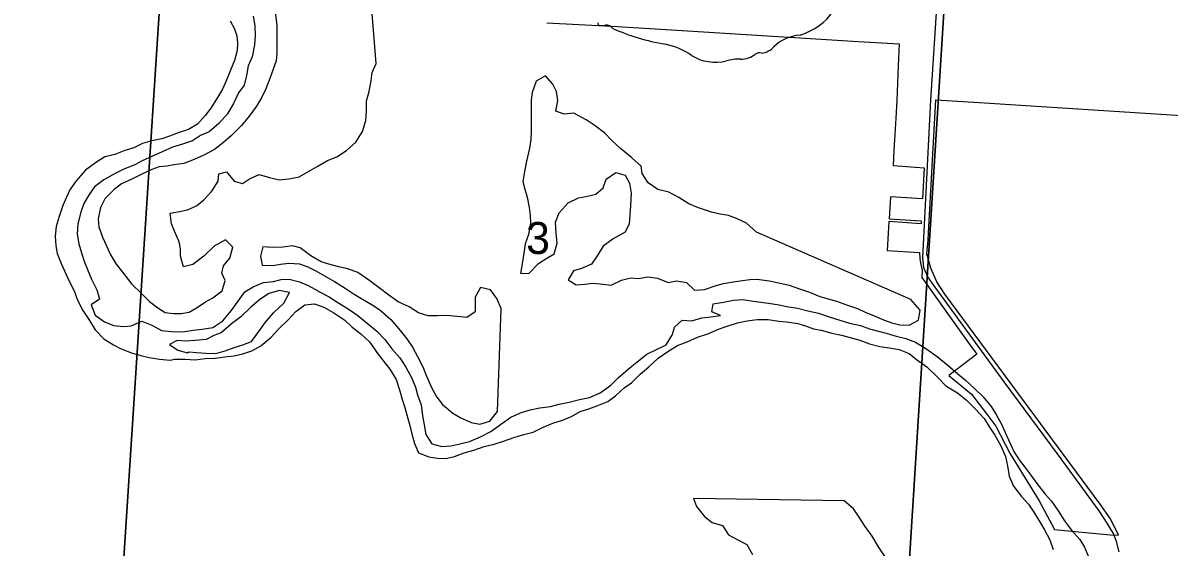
# Model space of a CAD drawing. Extents: x 114843 to 284848, y 317643 to 566895.
# Drawn here: x 207453 to 215376, y 334768 to 338396 of the extents above; entities that cross this region are included whole.
import ezdxf

# ---------------------------------------------------------------- set-up
doc = ezdxf.new("R2010")
doc.units = 0
for name, color, linetype in [('GM_X_Corporation', 7, 'Continuous'), ('GM_X_County_Road', 7, 'Continuous'), ('GM_X_Major_River', 7, 'Continuous'), ('GM_X_Minor_Lake', 7, 'Continuous'), ('GM_X_Section', 7, 'Continuous'), ('GM_X_Section_Text', 7, 'Continuous'), ('GM_X_State_Shield', 7, 'Continuous')]:
    doc.layers.add(name, color=color, linetype=linetype)

msp = doc.modelspace()

# ---------------------------------------------------------------- linework, layer by layer
at = {"layer": 'GM_X_Corporation'}
msp.add_lwpolyline([(211073.8, 338397.3), (211296.2, 338384.8), (211564.6, 338369.8), (211597.2, 338367.9), (211751, 338358.5), (211935.5, 338347.1), (212121.3, 338335.7), (212305.8, 338324.4), (212490.4, 338313), (212674.9, 338301.7), (212859.5, 338290.4), (213044.1, 338279), (213227.8, 338267.7), (213511.2, 338250.3), (213504.3, 338099), (213498.8, 337978.1), (213493.3, 337858.8), (213487, 337737.3), (213480.4, 337625.8), (213474.5, 337512.6), (213469, 337409.6), (213683.7, 337393.9), (213671.5, 337178.1), (213450.7, 337192.3), (213440.2, 337041), (213662.9, 337026.4), (213661.7, 337005), (213438.8, 337021.3), (213434.1, 336937.9), (213427.5, 336820.3), (213650.7, 336807.4), (213653.1, 336765.7), (213655.9, 336746.4), (213659.6, 336724.5), (213670.1, 336684.1), (213666.9, 336633), (213993.3, 336175.5), (214046.6, 336103.2), (213853.5, 335955.2), (214011.3, 335825.5), (214116.8, 335687.1), (214179.1, 335605.3), (214277.2, 335413.6), (214477.3, 335088.3), (214585.3, 334889.3), (214968.3, 334852.8), (215025.8, 334851.3), (214971.2, 334963.4), (214900.4, 335064.4), (214113.6, 336129.7), (213826.5, 336518.5), (213770.9, 336604.5), (213729.4, 336698), (213702.8, 336796.8), (213707.4, 336844.4), (213710.8, 336892.1), (213713, 336939.9), (213765, 337864.5), (214101.2, 337843.6), (215892.9, 337727.1)], dxfattribs=at)
at = {"layer": 'GM_X_County_Road'}
msp.add_lwpolyline([(215030.3, 334736.4), (215012.1, 334807.6), (214992.5, 334862.7), (214948.8, 334934.4), (214893, 335018), (214604.4, 335414.4), (214235.9, 335911.2), (213741.2, 336591.8), (213709.7, 336639.6), (213680.4, 336701.8), (213675.1, 336771.4), (213729.6, 337861.8), (213798.8, 338930.7), (213818.3, 339221.3)], dxfattribs=at)
at = {"layer": 'GM_X_Major_River'}
for points in [[(209044.3, 338442.2), (209056.7, 338376.2), (209059.1, 338306.1), (209053.5, 338244), (209038, 338161.8), (209010.4, 338097.6), (208998.8, 338031.4), (208983.3, 337965.2), (208943.6, 337912.9), (208908.1, 337838.6), (208866.6, 337766.3), (208807.1, 337699.8), (208741.5, 337641.3), (208679.7, 337616.9), (208626, 337580.5), (208556.2, 337556.1), (208486.4, 337535.6), (208414.7, 337503.2), (208349, 337474.7), (208277.3, 337442.2), (208225.5, 337413.9), (208149.8, 337383.4), (208090, 337353), (208012.4, 337310.4), (207946.7, 337262), (207911.1, 337207.7), (207873.5, 337145.4), (207853.9, 337085.2), (207832.4, 337004.9), (207828.9, 336934.8), (207839.3, 336866.8), (207857.6, 336804.8), (207878, 336740.9), (207900.3, 336689), (207926.6, 336623), (207965, 336549.2), (207983.4, 336483.2), (207925.7, 336444.8), (207952.1, 336372.9), (208016.3, 336327.2), (208082.4, 336301.6), (208148.3, 336294), (208200.2, 336300.3), (208276, 336330.8), (208344.1, 336303.2), (208410.2, 336267.6), (208480.1, 336260), (208558.1, 336258.5), (208629.9, 336268.9), (208691.8, 336275.3), (208765.6, 336287.8)], [(208886.7, 338409.2), (208915, 338355.3), (208931.3, 338305.3), (208935.6, 338255.3), (208933.9, 338205.2), (208916.3, 338135), (208888.7, 338068.8), (208861.2, 338000.5), (208833.6, 337936.3), (208790.1, 337867.9), (208752.5, 337805.6), (208712.8, 337755.3), (208659.3, 337694.9), (208597.6, 337658.5), (208533.8, 337638.1), (208466, 337611.6), (208412.2, 337593.2), (208344.3, 337580.8), (208278.5, 337562.4), (208220.8, 337532), (208157, 337513.6), (208089.2, 337485.1), (208019.4, 337468.7), (207953.7, 337428.2), (207886.1, 337375.7), (207820.6, 337303.2), (207777.1, 337240.9), (207753.4, 337190.7), (207729.8, 337132.5), (207704.3, 337056.2), (207682.7, 336988), (207675.1, 336919.9), (207679.5, 336853.8), (207689.8, 336799.8), (207716.2, 336729.9), (207740.5, 336680), (207772.9, 336608.1), (207807.3, 336542.2), (207829.6, 336476.2), (207866, 336406.4), (207912.4, 336336.6), (207952.7, 336270.7), (208013, 336209), (208079.2, 336167.4), (208131.3, 336139.7), (208203.4, 336112.1), (208267.4, 336094.5), (208325.4, 336080.8), (208397.4, 336069.2), (208471.4, 336061.7)], [(208765.6, 336287.8), (208835.3, 336334.3), (208892.8, 336402.7), (208940.3, 336471.1), (208987.9, 336535.5), (209045.6, 336569.9), (209115.3, 336600.3), (209185.2, 336606.8), (209237.1, 336619.1), (209293, 336621.5), (209365, 336603.9), (209425.1, 336578.2), (209495.2, 336538.6)], [(209295.5, 336529.4), (209227.5, 336542.9), (209151.8, 336522.5), (209088.1, 336480), (209028.5, 336427.6), (208959, 336361.1), (208895.3, 336312.6), (208823.8, 336252.1), (208772, 336231.7), (208720.2, 336205.4), (208644.3, 336198.9), (208580.4, 336192.5), (208518.5, 336198.1), (208466.7, 336169.8), (208522.9, 336130.1), (208590.9, 336112.5)], [(208590.9, 336112.5), (208600.9, 336118.5), (208652.8, 336114.9), (208716.8, 336109.2), (208786.7, 336107.7), (208850.5, 336126.1), (208920.3, 336152.6), (208972.1, 336168.9), (209033.9, 336191.3), (209083.4, 336259.7), (209129, 336324.1), (209184.5, 336388.5), (209256, 336457), (209295.5, 336529.4)], [(209495.2, 336538.6), (209503.3, 336534.6), (209569.4, 336501), (209629.6, 336461.3), (209701.7, 336417.7), (209767.9, 336370.1), (209832.2, 336318.4), (209900.4, 336262.7), (209954.7, 336205), (210003, 336141.2), (210057.4, 336077.5), (210099.7, 336013.6), (210138.1, 335941.8), (210166.5, 335873.9), (210180.7, 335821.9), (210205.1, 335751.9), (210215.6, 335675.9), (210227.9, 335613.9), (210238.3, 335547.9), (210280.7, 335482), (210348.7, 335464.4), (210410.6, 335468.8), (210472.4, 335483.2), (210540.3, 335499.6), (210616, 335532.2), (210687.7, 335568.6), (210755.3, 335617.1), (210824.9, 335667.6), (210892.6, 335698.1), (210960.4, 335718.5), (211026.3, 335731), (211100.1, 335741.4), (211160, 335757.8), (211229.8, 335770.3), (211299.6, 335790.7), (211369.4, 335803.2), (211443.2, 335835.7), (211516.8, 335888.2), (211568.4, 335940.6), (211635.9, 335999.1), (211699.6, 336049.5), (211765.2, 336104), (211832.9, 336134.5), (211898.6, 336168.9), (211944.1, 336239.3), (211957.8, 336289.4), (212009.4, 336337.8), (212077.4, 336334.2), (212145.2, 336354.7), (212209.1, 336361.1), (212274.9, 336371.5), (212214.9, 336397.1), (212224.5, 336451.3), (212296.4, 336463.7), (212364.2, 336478.2), (212430.1, 336480.6), (212502.1, 336469), (212554, 336463.3), (212608, 336455.6), (212682, 336444.1), (212734, 336432.4), (212808, 336422.8), (212878, 336403.2), (212952, 336387.7), (213026.1, 336362.1), (213100.1, 336338.5), (213168.2, 336318.9), (213242.2, 336301.3), (213306.3, 336279.7), (213368.3, 336262.1), (213420.3, 336248.4), (213490.4, 336226.8), (213556.4, 336211.1), (213622.5, 336185.5), (213702.6, 336137.9), (213772.9, 336088.3), (213849.1, 336024.7), (213915.4, 335967), (213969.6, 335923.3), (214031.9, 335865.6), (214090.2, 335807.9), (214146.5, 335740.1), (214180.8, 335686.3), (214219.2, 335614.4), (214251.6, 335540.5), (214279.9, 335480.6), (214304.2, 335430.7), (214340.5, 335372.8), (214378.8, 335321), (214421.1, 335265.2), (214461.3, 335207.3), (214519.7, 335135.6), (214564, 335085.8), (214610.3, 335018), (214652.7, 334950.2), (214701, 334884.4), (214759.3, 334820.6), (214791.6, 334768.8), (214822, 334696.8)], [(208471.4, 336061.7), (208503.3, 336067.9), (208575.2, 336068.3), (208643.1, 336064.7), (208713, 336073.2), (208782.9, 336075.6), (208848.8, 336084), (208912.6, 336092.4), (208972.5, 336104.8), (209036.3, 336127.2), (209098, 336161.7), (209167.6, 336218.2), (209221.1, 336278.6), (209288.7, 336343.1), (209340.3, 336399.5), (209401.9, 336445.9), (209467.8, 336452.3), (209533.9, 336428.7), (209602, 336389.1), (209678.2, 336339.5), (209728.5, 336289.7), (209788.7, 336244), (209851, 336186.3), (209899.3, 336114.5), (209937.6, 336064.7), (209989.9, 335998.9), (210034.3, 335929.1), (210056.7, 335857.2), (210077.1, 335783.2), (210093.4, 335733.2), (210113.8, 335659.2), (210128.1, 335609.3), (210142.4, 335551.3), (210158.8, 335485.3), (210187.1, 335421.4), (210259.2, 335393.8), (210333.2, 335380.2), (210385.2, 335382.5), (210437, 335394.9), (210502.8, 335421.3), (210570.6, 335439.8), (210640.4, 335464.2), (210710.2, 335480.7), (210776, 335501.1), (210845.7, 335525.6), (210907.6, 335544), (210979.3, 335564.4), (211045.1, 335596.9), (211116.8, 335625.4), (211182.6, 335645.8), (211246.4, 335672.2), (211306.1, 335706.6), (211357.9, 335723), (211427.7, 335747.4), (211497.4, 335775.9), (211549.2, 335814.3), (211608.7, 335870.7), (211660.5, 335905.1), (211720, 335965.5), (211779.7, 336016), (211845.2, 336076.5), (211910.9, 336120.9), (211978.5, 336163.4), (212044.3, 336189.8), (212116, 336220.3), (212187.8, 336244.8), (212261.5, 336275.3), (212315.3, 336295.6), (212393.1, 336320.1), (212458.9, 336334.6), (212528.8, 336343), (212604.7, 336343.5), (212678.7, 336331.9), (212730.7, 336326.2), (212810.6, 336314.7), (212862.7, 336299), (212918.7, 336279.3), (212970.7, 336269.6), (213044.8, 336248), (213112.8, 336234.4), (213186.8, 336214.9), (213238.8, 336201.2), (213304.9, 336175.5), (213376.9, 336156), (213442.9, 336148.3), (213510.9, 336134.8), (213579, 336109.1), (213631.2, 336065.4), (213701.4, 336015.8), (213773.7, 335946.1), (213832, 335884.4), (213914.2, 335834.8), (213976.5, 335785.1), (214036.7, 335725.4), (214099.1, 335657.7), (214131.3, 335605.9), (214171.7, 335542), (214212, 335474.2), (214244.5, 335396.3), (214258.9, 335330.3), (214271.3, 335260.2)], [(214271.3, 335260.2), (214301.6, 335190.3), (214356, 335118.6), (214404.3, 335064.8), (214440.6, 335010.9), (214484.9, 334939.1), (214515.2, 334887.2), (214551.6, 334817.4), (214574, 334751.4)]]:
    msp.add_lwpolyline(points, dxfattribs=at)
at = {"layer": 'GM_X_Minor_Lake'}
for points in [[(209894.7, 338114.1), (209806.3, 339212.4)], [(209199.7, 338455.4), (209207.1, 338375.2), (209208.6, 338305.1), (209207.8, 338184.9), (209203.4, 338132.8), (209183.1, 338074.9), (209160.6, 338011), (209132.2, 337939), (209101.8, 337877.1), (209067.4, 337819.3), (209017, 337751.5), (208964.6, 337685.8), (208892.2, 337614.1), (208839.9, 337568.4), (208777.6, 337520.8), (208703.4, 337481.2), (208637.3, 337449.6), (208565.2, 337424), (208497.2, 337412.5), (208447.2, 337404.8), (208395.2, 337399.2), (208343.1, 337381.5), (208274.9, 337349.9), (208206.8, 337314.3), (208134.6, 337282.7), (208084.4, 337243), (208020, 337179.4), (207989.6, 337117.5), (207973.1, 337039.4), (207976.7, 336985.3), (208004.2, 336913), (208029.7, 336852.7), (208055.3, 336794.5), (208096.8, 336726.1), (208140.4, 336671.7), (208203.8, 336591.1), (208275.2, 336520.5), (208328.8, 336468.1), (208384.5, 336423.6), (208436.2, 336391.2), (208494.1, 336384.8), (208548, 336384.5), (208602, 336394.1), (208658.2, 336425.8), (208714.4, 336465.5), (208766.6, 336493.2), (208830.9, 336540.8), (208851.3, 336612.8), (208827.7, 336663), (208840, 336715), (208884.4, 336766.8), (208904.9, 336842.8), (208853.3, 336895.2), (208775, 336849.7), (208702.6, 336782.1), (208628.3, 336724.5), (208562.2, 336706.9), (208542.8, 336781.2), (208543.1, 336831.2), (208533.5, 336881.4), (208500, 336955.7), (208480.4, 337006), (208470.9, 337078.1), (208534.9, 337091.7), (208590.9, 337101.4), (208653.1, 337129), (208703.3, 337170.7)], [(208703.3, 337170.7), (208759.7, 337232.4), (208802.1, 337300.2), (208806.5, 337352.3), (208860.5, 337366), (208914, 337299.5), (208969.8, 337285.1), (209020, 337316.8), (209086.1, 337346.4), (209157.9, 337325.9), (209223.8, 337309.4), (209291.8, 337317), (209361.8, 337330.5), (209438, 337374.1), (209488.1, 337401.8), (209558.4, 337443.4), (209622.5, 337469), (209690.7, 337512.6), (209755.1, 337570.2), (209801.5, 337644), (209824, 337720), (209828.4, 337784.1), (209828.9, 337856.2), (209847.4, 337922.2), (209859.9, 337998.2), (209866.3, 338052.2), (209894.7, 338114.1)], [(212524.2, 336946.5), (212454.7, 337011), (212386.9, 337041.5), (212331.1, 337062), (212273.3, 337072.4), (212213.4, 337086.8), (212123.7, 337115.5), (212056, 337144), (211986.3, 337186.5), (211918.6, 337225), (211842.8, 337243.6), (211775.2, 337288.1), (211733.7, 337354.5), (211726.1, 337404.6), (211662.5, 337463.1), (211585, 337525.8), (211523.5, 337582.3), (211475.9, 337632.7), (211408.3, 337683.2), (211346.6, 337725.7), (211261, 337770.4), (211195, 337764.8), (211137.2, 337785.2), (211151.7, 337857.2), (211142.2, 337921.4), (211116.5, 337971.7), (211065, 338030.1), (211000.8, 337992.5), (210972.3, 337914.5), (210965.9, 337862.5), (210967.6, 337810.4), (210966.4, 337646.2), (210964, 337588.1), (210955.6, 337528), (210935, 337440), (210920.6, 337368), (210908.1, 337298), (210921.7, 337245.8), (210939.3, 337189.6), (210952.8, 337117.4), (210960.4, 337063.3), (210962.1, 337009.2), (210947.5, 336931.1), (210925.1, 336867.2), (210916.7, 336803.1), (210904.2, 336729.1), (210891.7, 336663.1), (210949.7, 336660.7), (211016.1, 336730.3), (211074.3, 336768), (211124.4, 336797.7), (211146.9, 336871.7), (211139.4, 336941.8), (211134, 337018), (211160.4, 337081.9), (211222.8, 337149.6), (211292.9, 337185.2), (211345, 337194.9), (211413, 337210.4), (211463.3, 337254.2), (211485.7, 337314.1), (211551.9, 337361.7), (211615.7, 337341.3), (211645.3, 337287), (211656.8, 337216.8), (211654.2, 337132.7), (211647.8, 337066.6), (211643.4, 337004.5), (211617, 336948.6), (211532.8, 336901.1), (211464.5, 336851.5), (211422.1, 336783.7), (211383.7, 336725.8), (211313.6, 336696.3), (211259.5, 336680.6), (211221.1, 336618.8), (211276.8, 336582.3), (211338.8, 336587.9), (211388.8, 336595.6), (211442.7, 336591.2), (211518.6, 336580.7), (211590.8, 336616.3), (211654.8, 336631.8), (211708.7, 336627.5), (211772.7, 336639.1), (211840.6, 336628.6), (211914.3, 336600), (211970.4, 336609.7), (212040.2, 336599.2), (212095.8, 336546.7), (212163.8, 336550.3), (212245.9, 336577.7), (212295.9, 336593.4), (212362, 336605), (212412, 336610.7), (212477.9, 336620.2), (212529.9, 336621.9), (212611.8, 336611.3), (212677.6, 336596.8), (212749.4, 336580.3), (212821.2, 336555.8)], [(213592, 336482.4), (212524.2, 336946.5)], [(210760.2, 336419.6), (210728.7, 336487.9), (210685.2, 336548.3), (210617.3, 336564.8), (210578.9, 336498.9), (210578.2, 336396.8), (210522, 336357.1), (210454.1, 336363.5), (210382.2, 336370), (210318.3, 336368.5), (210254.3, 336368.9), (210186.5, 336389.4), (210122.9, 336429.9), (210047.2, 336466.5), (209981.6, 336511), (209916, 336561.5), (209850.4, 336610), (209768.8, 336668.7), (209699.1, 336693.2), (209645.2, 336705.6), (209583.4, 336722), (209513.6, 336742.5), (209443.9, 336783.1), (209370.4, 336839.7), (209316.5, 336854.1), (209250.5, 336844.5), (209176.6, 336841), (209110.7, 336845.4), (209094.3, 336781.4), (209105.8, 336719.3), (209179.7, 336716.8), (209233.7, 336726.4), (209291.7, 336734), (209365.6, 336727.5), (209421.4, 336707.1), (209473.2, 336682.7), (209542.9, 336642.2), (209606.6, 336605.7), (209680.2, 336561.1), (209741.8, 336518.6), (209801.5, 336484.2), (209867.2, 336445.7), (209920.9, 336409.2), (209996.4, 336342.6), (210061.8, 336266), (210107.4, 336209.6), (210146.9, 336151.3), (210180.4, 336086.9), (210217.9, 336016.5), (210243.4, 335950.3), (210280.8, 335867.9), (210314.4, 335805.5), (210354, 335755.2), (210425.5, 335694.6), (210481.2, 335662.2), (210550.9, 335629.6), (210610.8, 335619.2), (210680.9, 335638.8), (210733.3, 335706.5)], [(212821.2, 336555.8), (212891, 336531.3), (212962.7, 336502.8), (213018.5, 336486.3), (213076.4, 336469.9), (213154.1, 336443.3), (213221.9, 336418.8), (213279.6, 336392.4), (213333.4, 336372), (213401.2, 336341.5), (213459, 336321.1), (213514.8, 336306.7), (213580.7, 336304.2), (213644.9, 336339.8), (213655.4, 336407.9), (213592, 336482.4)], [(210733.3, 335706.5), (210760.2, 336419.6)], [(212087.9, 335104.3), (212109.5, 335050.1), (212164.9, 334979.6), (212216.6, 334939.1), (212288.4, 334918.6), (212329.9, 334854.2), (212395.6, 334817.7), (212457.4, 334787.2), (212496.8, 334716.8)], [(213130.8, 335089.2), (212087.9, 335104.3)], [(213413.9, 334700.6), (213368.4, 334769), (213324.9, 334843.4), (213275.4, 334909.9), (213233.9, 334976.3), (213194.4, 335032.7), (213130.8, 335089.2)]]:
    msp.add_lwpolyline(points, dxfattribs=at)
at = {"layer": 'GM_X_Section'}
msp.add_lwpolyline([(204087.8, 340018.2), (208485.6, 339850.8), (208132.8, 334409.4)], dxfattribs=at)
for points in [[(208485.6, 339850.8), (213886.9, 339535.8), (213546, 334098.4), (208132.8, 334409.4)], [(213886.9, 339535.8), (219114.3, 339232.4), (218755.3, 333824.9), (213546, 334098.4)]]:
    msp.add_lwpolyline(points, close=True, dxfattribs=at)
at = {"layer": 'GM_X_State_Shield'}
for centre, major_axis, start_param, end_param in [((212648.2, 338651.4), (461.6, 3.3), 5.101753, 6.440018), ((211446.4, 338393.7), (20.3, 0.1), 3.00124, 4.508301), ((211448.7, 338501.9), (155.2, 1.1), 4.665946, 4.897461), ((211481.6, 338335.3), (56, 0.4), 0.519207, 1.627899), ((212181.4, 339289.8), (1332.8, 9.6), 4.195996, 4.488959), ((212846.8, 338109.5), (252.8, 1.8), 1.647645, 2.488434), ((211793.9, 337923.8), (417, 3), 0.823519, 1.323588), ((212414.8, 338257.7), (141, 1), 4.691044, 5.507374), ((212543, 338156.3), (39.7, 0.3), 1.147584, 2.315152), ((212525.1, 338301.4), (149.1, 1.1), 4.937069, 5.64225), ((212242, 338335.6), (264.6, 1.9), 4.026481, 4.996735), ((212397.5, 337971.3), (217.4, 1.6), 1.495662, 1.94098)]:
    msp.add_ellipse(centre, major_axis=major_axis, ratio=0.8, start_param=start_param, end_param=end_param, dxfattribs=at)

# ---------------------------------------------------------------- texts
at = {"layer": 'GM_X_Section_Text'}
msp.add_text('3', height=221, rotation=0.41344, dxfattribs=at).set_placement((210932.1, 336796.3))

doc.saveas('drawing.dxf')
